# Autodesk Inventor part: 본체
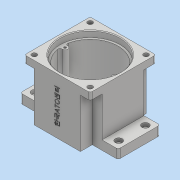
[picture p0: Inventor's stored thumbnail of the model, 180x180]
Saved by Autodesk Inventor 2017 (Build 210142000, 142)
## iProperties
Part Number: 본체
Material: 일반
Document SubType Name: Modeling
Designer: user
Density: 1 g/cm^3
Appearance: 기본값
Author: user
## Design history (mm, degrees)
sketch "스케치11"
  geometry: L1 (-70, -30)-(70, -30); L2 (70, -30)-(70, 30); L3 (70, 30)-(-70, 30); L4 (-70, 30)-(-70, -30); L5 (-70, -30)-(70, 30); L6 (70, -30)-(-70, 30); L7 (-33, 47)-(33, 47); L8 (33, 47)-(33, -47); L9 (33, -47)-(-33, -47); L10 (-33, -47)-(-33, 47); L11 (-33, 47)-(33, -47); L12 (33, 47)-(-33, -47); 1 further point
  constraints: 24 end point, 4 midpoint, 4 parallel, 2 horizontal, 2 perpendicular
  dimensions: "d37" = 140 distance of L3.end L2.end; "d38" = 60 distance of L2.end L1.end; "d39" = 66 distance of L8.end L9.end; "d40" = 94 distance of L7.end L8.end
extrude "돌출10" new body sketch "스케치11" distance "d41" = 13; taper "d42" = 0 deg
sketch "스케치12"
  geometry: L1 (-47, 30)-(47, 30); L2 (47, 30)-(47, -30); L3 (47, -30)-(-47, -30); L4 (-47, -30)-(-47, 30); L5 (-47, 30)-(47, -30); L6 (47, 30)-(-47, -30); L7 (-33, 47)-(33, 47); L8 (33, 47)-(33, -47); L9 (33, -47)-(-33, -47); L10 (-33, -47)-(-33, 47); L11 (-33, 47)-(33, -47); L12 (33, 47)-(-33, -47); 1 further point
  constraints: 24 end point, 4 midpoint, 4 parallel, 2 horizontal, 2 perpendicular
  dimensions: "d43" = 94 distance of L2.end L3.end; "d44" = 60 distance of L1.end L2.end; "d45" = 66 distance of L8.end L9.end; "d46" = 94 distance of L7.end L8.end
extrude "돌출11" join sketch "스케치12" distance "d47" = 57; taper "d48" = 0 deg
sketch "스케치13"
  geometry: L1 (-47, -47)-(47, -47); L2 (47, -47)-(47, 47); L3 (47, 47)-(-47, 47); L4 (-47, 47)-(-47, -47); L5 (-47, -47)-(47, 47); L6 (47, -47)-(-47, 47); 1 further point
  constraints: 12 end point, 2 midpoint, 2 parallel, 1 horizontal, 1 perpendicular
  dimensions: "d49" = 94 distance of L3.end L2.end; "d50" = 94 distance of L2.end L1.end
extrude "돌출12" join sketch "스케치13" distance "d51" = 10; taper "d52" = 0 deg
sketch "스케치14"
  geometry: C1 r 43 at (0, 0); 1 further point
  constraints: 1 centre point, 1 coincident
  dimensions: "d53" = 86 diameter of C1
extrude "돌출13" cut sketch "스케치14" distance "d54" = 9; taper "d55" = 0 deg
sketch "스케치15"
  geometry: C1 r 40 at (0, 0); 1 further point
  constraints: 1 centre point, 1 coincident
  dimensions: "d56" = 80 diameter of C1
extrude "돌출14" cut sketch "스케치15" distance "d57" = 62; taper "d58" = 0 deg
sketch "스케치16"
  geometry: C1 r 27.5 at (0, -11); 1 further point
  constraints: 1 centre point, 1 vertical alignment
  dimensions: "d59" = 55 diameter of C1; "d60" = 11 distance of point (0, 0) C1.centre
extrude "돌출15" join sketch "스케치16" distance "d61" = 7; taper "d62" = 0 deg
sketch "스케치17"
  geometry: C1 r 21 at (0, -11); C2 r 15 at (0, 20); 1 further point
  constraints: 2 centre point, 2 vertical alignment
  dimensions: "d63" = 42 diameter of C1; "d64" = 30 diameter of C2; "d65" = 11 distance of point (0, 0) C1.centre; "d66" = 20 distance of C2.centre point (0, 0)
extrude "돌출16" join sketch "스케치17" distance "d67" = 7; taper "d68" = 0 deg
sketch "스케치22"
  geometry: C1 r 11 at (0, 20); A1 r 15 centre (0, 20) between (8.978, 7.984) and (-8.978, 7.984) reference; 1 further point
  constraints: 1 centre point, 1 concentric
  dimensions: "d78" = 22 diameter of C1
extrude "돌출20" cut sketch "스케치22" distance "d79" = 7; taper "d80" = 0 deg
sketch "스케치23"
  geometry: C1 r 9.5 at (0, 0); C2 r 11 at (0, 0) reference; 1 further point
  constraints: 1 centre point, 1 concentric
  dimensions: "d81" = 19 diameter of C1
extrude "돌출21" cut sketch "스케치23" distance "d82" = 3; taper "d83" = 0 deg
sketch "스케치24"
  geometry: 2 further points
  dimensions: "d84" = 60 horizontal distance of point (-60, -19) point (0, 0); "d85" = 19 vertical distance of point (0, 0) point (-60, -19)
hole "구멍1" sketch "스케치24" at (-60, -19) diameter "d86" = 4.5; stored, may be unused: countersink angle "d90" = 90 deg, drill point angle "d92" = 0 deg; dims "d87" = 6, "d88" = 10, "d89" = 5, "d91" = 13
sketch "스케치25"
  geometry: C1 r 3.5 at (40, -40); 1 further point
  constraints: 1 centre point
  dimensions: "d99" = 7 diameter of C1; "d100" = 40 horizontal distance of C1.centre point (0, 0); "d101" = 40 horizontal distance of point (0, 0) C1.centre
extrude "돌출22" cut sketch "스케치25" stored distance "d102" = 3; taper "d103" = 0 deg
sketch "스케치26"
  geometry: A1 r 4 centre (36, 0) between (36.19, 3.995) and (36.19, -3.995); A2 r 40 centre (0, 0) between (39.279, 7.559) and (39.279, -7.559) reference; A3 r 3 centre (36.333, 6.992) between (36.19, 3.995) and (39.279, 7.559); A4 r 3 centre (36.333, -6.992) between (39.279, -7.559) and (36.19, -3.995); 1 further point
  constraints: 8 point on circle, 4 tangent, 3 centre point, 1 horizontal alignment
  dimensions: "d110" = 8 diameter of A1; "d111" = 36 distance of point (0, 0) A1.centre; "d124" = 3 radius of A3; "d125" = 3 radius of A4
extrude "돌출23" join sketch "스케치26" stored distance "d114" = 3; taper "d115" = 0 deg
node "작업 평면1"
sketch "스케치27"
  geometry: 2 further points
  constraints: 1 horizontal alignment
  dimensions: "d116" = 36 distance of point (0, 0) point (36, 0)
hole "구멍2" sketch "스케치27" at (36, 0) diameter "d117" = 3.242; stored, may be unused: countersink angle "d121" = 90 deg, drill point angle "d123" = 118 deg; dims "d118" = 7, "d119" = 10, "d120" = 5, "d122" = 9
sketch "스케치28"
  geometry: L1 (66, 0)-(0, 0) reference; L2 (-14, 80)-(80, 80) reference; 3 further points
  constraints: 1 midpoint, 1 vertical alignment, 1 other
  dimensions: "d126" = 40 distance from line of L2 point (33, 40)
feature "엠보싱1" sketch "스케치28" dims "d37" = 140, "d38" = 60, "d45" = 66, "d46" = 94, "d127" = 0.5, "d128" = 0
fillet "모깎기1" dims "d129" = 3
fillet "모깎기2" dims "d130" = 3
chamfer "모따기2" distance "d134" = 1; stored, may be unused: second distance "d135" = 2, angle "d136" = 30 deg
chamfer "모따기3" distance "d137" = 1; stored, may be unused: second distance "d138" = 2, angle "d139" = 30 deg
fillet "모깎기3" dims "d140" = 3
fillet "모깎기4" dims "d141" = 3
sketch "스케치29"
  geometry: C1 r 17.5 at (0, -11); A1 r 21 centre (0, -11) between (-12.163, 6.119) and (12.163, 6.119) reference; 1 further point
  constraints: 1 centre point, 1 concentric
  dimensions: "d142" = 35 diameter of C1
extrude "돌출24" cut sketch "스케치29" distance "d143" = 10; taper "d144" = 0 deg
sketch "스케치30"
  geometry: C1 r 16 at (0, 0); C2 r 27.5 at (0, 0) reference; 1 further point
  constraints: 1 centre point, 1 concentric
  dimensions: "d145" = 32 diameter of C1
extrude "돌출25" cut sketch "스케치30" distance "d146" = 8.3; taper "d147" = 0 deg
sketch "스케치31"
  geometry: C1 r 12.5 at (0, 0); C2 r 16 at (0, 0) reference; 1 further point
  constraints: 1 centre point, 1 concentric
  dimensions: "d148" = 25 diameter of C1
extrude "돌출26" cut sketch "스케치31" stored distance "d149" = 8.3; taper "d150" = 0 deg
chamfer "모따기4" distance "d151" = 0.8; stored, may be unused: second distance "d152" = 2, angle "d153" = 30 deg
chamfer "모따기5" distance "d154" = 1; stored, may be unused: second distance "d155" = 2, angle "d156" = 30 deg
node "솔리드3"
pattern_linear "직사각형 패턴1" dims "d95" = 120, "d98" = -38
pattern_linear "직사각형 패턴2" dims "d106" = -80, "d109" = 80
mirror "미러1"
